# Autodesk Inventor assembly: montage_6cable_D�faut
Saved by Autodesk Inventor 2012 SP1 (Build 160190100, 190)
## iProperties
Created: 2011-01
Part Number: montage_6cable_D�faut
Document SubType Name: Assembly
Designer: eric
Mass: 9.7659 g
Surface Area: 225.622 cm^2
Volume: 9.7659 cm^3
Density: 1 g/cm^3
Author: eric
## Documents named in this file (6)
- D:\Cours\Inventor salle SI\chariot_de_golf_2008\chariot_de_golf_trolem\montage_6cable_Defaut.iam
- D:\Cours\Inventor salle SI\chariot_de_golf_2008\chariot_de_golf_trolem\11tube-cable_Defaut.ipt
- D:\Cours\Inventor salle SI\chariot_de_golf_2008\chariot_de_golf_trolem\6cable_Defaut.ipt
- D:\Cours\Inventor salle SI\chariot_de_golf_2008\chariot_de_golf_trolem\57soufflet_Defaut.ipt
- D:\Cours\Inventor salle SI\chariot_de_golf_2008\chariot_de_golf_trolem\10gaine_Defaut.ipt
- D:\Cours\Inventor salle SI\chariot_de_golf_2008\chariot_de_golf_trolem\54butee_de cable_Defaut.ipt
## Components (6 placed, 5 different names)
1. 11tube-cable_Defaut:1
2. 6cable_Defaut:1
3. 57soufflet_Defaut:1
4. 57soufflet_Defaut:2
5. 10gaine_Defaut:1
6. 54butee_de cable_Defaut:1
